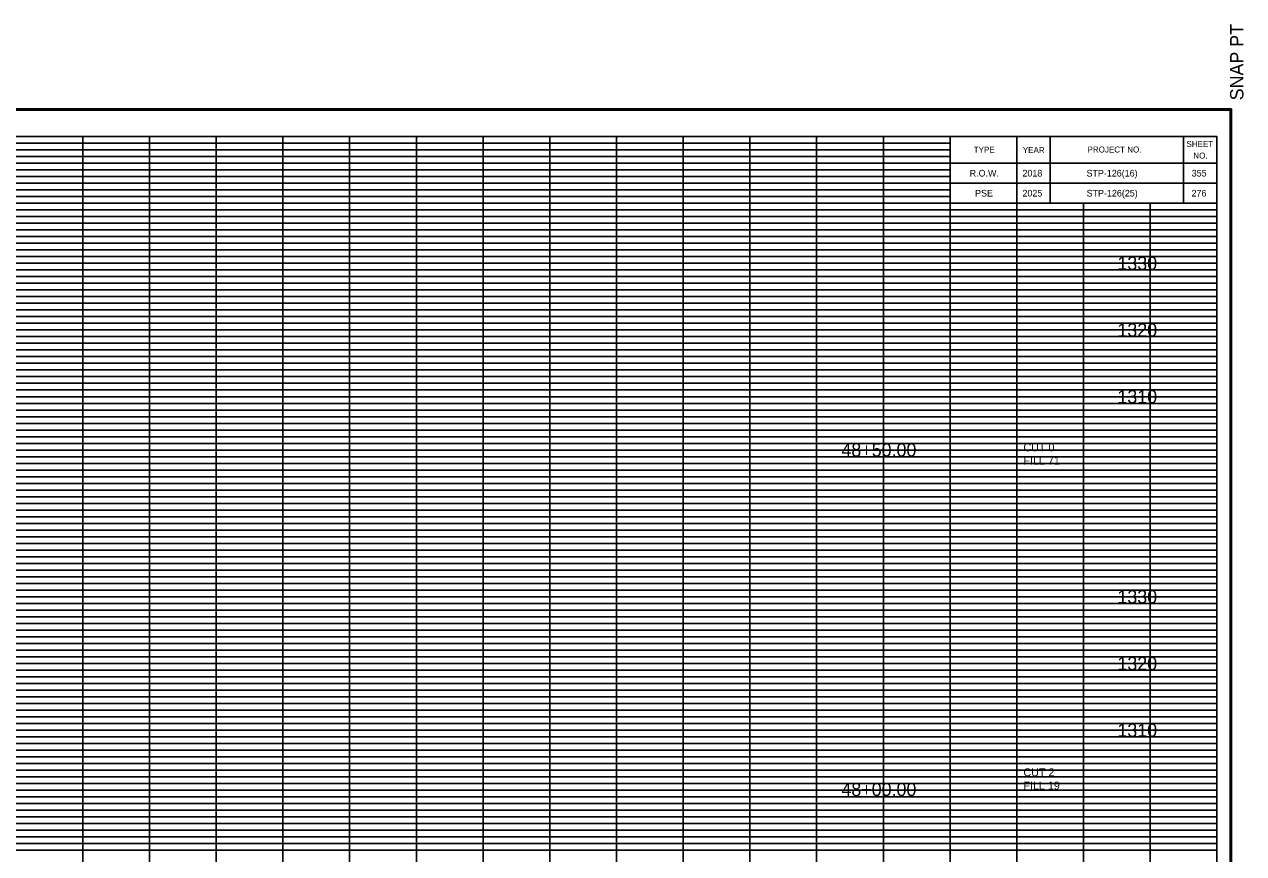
# Model space of a CAD drawing. Extents: x 980 to 1324, y 978 to 1497.
# Drawn here: x 1141.2 to 1324, y 1102.5 to 1226.8 of the extents above; entities that cross this region are included whole.
import ezdxf

# ---------------------------------------------------------------- set-up
doc = ezdxf.new("R2010")
doc.units = 0
for name, color, linetype in [('DESIGN - SCRATCH - User 1', 7, 'Continuous'), ('DESIGN - SHEET - Corner Text', 7, 'Continuous'), ('DESIGN - SHEET - Light Grid', 7, 'Continuous'), ('DESIGN - SHEET - Linework', 7, 'Continuous'), ('DESIGN - SHEET - Plot Shape', 7, 'Continuous'), ('DESIGN - TYPICAL - Finished Grade and Subgrade', 7, 'Continuous'), ('DESIGN - TYPICAL - Text', 7, 'Continuous')]:
    doc.layers.add(name, color=color, linetype=linetype)

# ---------------------------------------------------------------- blocks, each defined once
blk = doc.blocks.new('XSTSHT')
at = {"layer": 'DESIGN - SCRATCH - User 1'}
for p, q in [((28.5, 20.45), (28.5, 20.45)), ((29.24, 20.45), (29.24, 20.45)), ((30.49, 20.45), (30.49, 20.45)), ((31.74, 20.45), (31.74, 20.45)), ((28.5, 20.15), (28.5, 20.15)), ((29.24, 20.15), (29.24, 20.15)), ((30.49, 20.15), (30.49, 20.15)), ((31.74, 20.15), (31.74, 20.15))]:
    blk.add_line(p, q, dxfattribs=at)
at = {"layer": 'DESIGN - SHEET - Light Grid'}
for p, q in [((8, 20.9), (16, 20.9)), ((16, 20.9), (24, 20.9)), ((24, 20.9), (28, 20.9)), ((8, 20.8), (16, 20.8)), ((8, 20.7), (16, 20.7)), ((16, 20.8), (24, 20.8)), ((16, 20.7), (24, 20.7)), ((24, 20.8), (28, 20.8)), ((24, 20.7), (28, 20.7)), ((8, 20.6), (16, 20.6)), ((8, 20.5), (16, 20.5)), ((16, 20.6), (24, 20.6)), ((16, 20.5), (24, 20.5)), ((24, 20.6), (28, 20.6)), ((24, 20.5), (28, 20.5)), ((8, 20.4), (16, 20.4)), ((8, 20.3), (16, 20.3)), ((16, 20.4), (24, 20.4)), ((16, 20.3), (24, 20.3)), ((24, 20.4), (28, 20.4)), ((24, 20.3), (28, 20.3)), ((8, 20.2), (16, 20.2)), ((16, 20.2), (24, 20.2)), ((24, 20.2), (28, 20.2)), ((8, 20.1), (16, 20.1)), ((16, 20.1), (24, 20.1)), ((24, 20.1), (28, 20.1)), ((8, 19.9), (16, 19.9)), ((8, 19.8), (16, 19.8)), ((16, 19.9), (24, 19.9)), ((16, 19.8), (24, 19.8)), ((24, 19.9), (32, 19.9)), ((24, 19.8), (32, 19.8)), ((8, 19.7), (16, 19.7)), ((8, 19.6), (16, 19.6)), ((16, 19.7), (24, 19.7)), ((16, 19.6), (24, 19.6)), ((24, 19.7), (32, 19.7)), ((24, 19.6), (32, 19.6)), ((8, 19.5), (16, 19.5)), ((8, 19.4), (16, 19.4)), ((16, 19.5), (24, 19.5)), ((16, 19.4), (24, 19.4)), ((24, 19.5), (32, 19.5)), ((24, 19.4), (32, 19.4)), ((8, 19.3), (16, 19.3)), ((8, 19.2), (16, 19.2)), ((16, 19.3), (24, 19.3)), ((16, 19.2), (24, 19.2)), ((24, 19.3), (32, 19.3)), ((24, 19.2), (32, 19.2)), ((8, 19.1), (16, 19.1)), ((16, 19.1), (24, 19.1)), ((24, 19.1), (32, 19.1)), ((8, 18.9), (16, 18.9)), ((16, 18.9), (24, 18.9)), ((24, 18.9), (32, 18.9)), ((8, 18.8), (16, 18.8)), ((8, 18.7), (16, 18.7)), ((16, 18.8), (24, 18.8)), ((16, 18.7), (24, 18.7)), ((24, 18.8), (32, 18.8)), ((24, 18.7), (32, 18.7)), ((8, 18.6), (16, 18.6)), ((8, 18.5), (16, 18.5)), ((16, 18.6), (24, 18.6)), ((16, 18.5), (24, 18.5)), ((24, 18.6), (32, 18.6)), ((24, 18.5), (32, 18.5)), ((8, 18.4), (16, 18.4)), ((8, 18.3), (16, 18.3)), ((16, 18.4), (24, 18.4)), ((16, 18.3), (24, 18.3)), ((24, 18.4), (32, 18.4)), ((24, 18.3), (32, 18.3)), ((8, 18.2), (16, 18.2)), ((8, 18.1), (16, 18.1)), ((16, 18.2), (24, 18.2)), ((16, 18.1), (24, 18.1)), ((24, 18.2), (32, 18.2)), ((24, 18.1), (32, 18.1)), ((8, 17.9), (16, 17.9)), ((8, 17.8), (16, 17.8)), ((16, 17.9), (24, 17.9)), ((16, 17.8), (24, 17.8)), ((24, 17.9), (32, 17.9)), ((24, 17.8), (32, 17.8)), ((8, 17.7), (16, 17.7)), ((8, 17.6), (16, 17.6)), ((16, 17.7), (24, 17.7)), ((16, 17.6), (24, 17.6)), ((24, 17.7), (32, 17.7)), ((24, 17.6), (32, 17.6)), ((8, 17.5), (16, 17.5)), ((8, 17.4), (16, 17.4)), ((16, 17.5), (24, 17.5)), ((16, 17.4), (24, 17.4)), ((24, 17.5), (32, 17.5)), ((24, 17.4), (32, 17.4)), ((8, 17.3), (16, 17.3)), ((8, 17.2), (16, 17.2)), ((16, 17.3), (24, 17.3)), ((16, 17.2), (24, 17.2)), ((24, 17.3), (32, 17.3)), ((24, 17.2), (32, 17.2)), ((8, 17.1), (16, 17.1)), ((16, 17.1), (24, 17.1)), ((24, 17.1), (32, 17.1)), ((8, 16.9), (16, 16.9)), ((16, 16.9), (24, 16.9)), ((24, 16.9), (32, 16.9)), ((8, 16.8), (16, 16.8)), ((8, 16.7), (16, 16.7)), ((16, 16.8), (24, 16.8)), ((16, 16.7), (24, 16.7)), ((24, 16.8), (32, 16.8)), ((24, 16.7), (32, 16.7)), ((8, 16.6), (16, 16.6)), ((8, 16.5), (16, 16.5)), ((16, 16.6), (24, 16.6)), ((16, 16.5), (24, 16.5)), ((24, 16.6), (32, 16.6)), ((24, 16.5), (32, 16.5)), ((8, 16.4), (16, 16.4)), ((8, 16.3), (16, 16.3)), ((16, 16.4), (24, 16.4)), ((16, 16.3), (24, 16.3)), ((24, 16.4), (32, 16.4)), ((24, 16.3), (32, 16.3)), ((8, 16.2), (16, 16.2)), ((8, 16.1), (16, 16.1)), ((16, 16.2), (24, 16.2)), ((16, 16.1), (24, 16.1)), ((24, 16.2), (32, 16.2)), ((24, 16.1), (32, 16.1)), ((8, 15.9), (16, 15.9)), ((16, 15.9), (24, 15.9)), ((24, 15.9), (32, 15.9)), ((8, 15.8), (16, 15.8)), ((16, 15.8), (24, 15.8)), ((24, 15.8), (32, 15.8)), ((8, 15.7), (16, 15.7)), ((8, 15.6), (16, 15.6)), ((16, 15.7), (24, 15.7)), ((16, 15.6), (24, 15.6)), ((24, 15.7), (32, 15.7)), ((24, 15.6), (32, 15.6)), ((8, 15.5), (16, 15.5)), ((8, 15.4), (16, 15.4)), ((16, 15.5), (24, 15.5)), ((16, 15.4), (24, 15.4)), ((24, 15.5), (32, 15.5)), ((24, 15.4), (32, 15.4)), ((8, 15.3), (16, 15.3)), ((8, 15.2), (16, 15.2)), ((16, 15.3), (24, 15.3)), ((16, 15.2), (24, 15.2)), ((24, 15.3), (32, 15.3)), ((24, 15.2), (32, 15.2)), ((8, 15.1), (16, 15.1)), ((16, 15.1), (24, 15.1)), ((24, 15.1), (32, 15.1)), ((8, 14.9), (16, 14.9)), ((16, 14.9), (24, 14.9)), ((24, 14.9), (32, 14.9)), ((8, 14.8), (16, 14.8)), ((8, 14.7), (16, 14.7)), ((16, 14.8), (24, 14.8)), ((16, 14.7), (24, 14.7)), ((24, 14.8), (32, 14.8)), ((24, 14.7), (32, 14.7)), ((8, 14.6), (16, 14.6)), ((8, 14.5), (16, 14.5)), ((16, 14.6), (24, 14.6)), ((16, 14.5), (24, 14.5)), ((24, 14.6), (32, 14.6)), ((24, 14.5), (32, 14.5)), ((8, 14.4), (16, 14.4)), ((8, 14.3), (16, 14.3)), ((16, 14.4), (24, 14.4)), ((16, 14.3), (24, 14.3)), ((24, 14.4), (32, 14.4)), ((24, 14.3), (32, 14.3)), ((8, 14.2), (16, 14.2)), ((8, 14.1), (16, 14.1)), ((16, 14.2), (24, 14.2)), ((16, 14.1), (24, 14.1)), ((24, 14.2), (32, 14.2)), ((24, 14.1), (32, 14.1)), ((8, 13.9), (16, 13.9)), ((16, 13.9), (24, 13.9)), ((24, 13.9), (32, 13.9)), ((8, 13.8), (16, 13.8)), ((16, 13.8), (24, 13.8)), ((24, 13.8), (32, 13.8)), ((8, 13.7), (16, 13.7)), ((8, 13.6), (16, 13.6)), ((16, 13.7), (24, 13.7)), ((16, 13.6), (24, 13.6)), ((24, 13.7), (32, 13.7)), ((24, 13.6), (32, 13.6)), ((8, 13.5), (16, 13.5)), ((8, 13.4), (16, 13.4)), ((16, 13.5), (24, 13.5)), ((16, 13.4), (24, 13.4)), ((24, 13.5), (32, 13.5)), ((24, 13.4), (32, 13.4)), ((8, 13.3), (16, 13.3)), ((8, 13.2), (16, 13.2)), ((16, 13.3), (24, 13.3)), ((16, 13.2), (24, 13.2)), ((24, 13.3), (32, 13.3)), ((24, 13.2), (32, 13.2)), ((8, 13.1), (16, 13.1)), ((16, 13.1), (24, 13.1)), ((24, 13.1), (32, 13.1)), ((8, 12.9), (16, 12.9)), ((8, 12.8), (16, 12.8)), ((16, 12.9), (24, 12.9)), ((16, 12.8), (24, 12.8)), ((24, 12.9), (32, 12.9)), ((24, 12.8), (32, 12.8)), ((8, 12.7), (16, 12.7)), ((16, 12.7), (24, 12.7)), ((24, 12.7), (32, 12.7)), ((8, 12.6), (16, 12.6)), ((8, 12.5), (16, 12.5)), ((16, 12.6), (24, 12.6)), ((16, 12.5), (24, 12.5)), ((24, 12.6), (32, 12.6)), ((24, 12.5), (32, 12.5)), ((8, 12.4), (16, 12.4)), ((8, 12.3), (16, 12.3)), ((16, 12.4), (24, 12.4)), ((16, 12.3), (24, 12.3)), ((24, 12.4), (32, 12.4)), ((24, 12.3), (32, 12.3)), ((8, 12.2), (16, 12.2)), ((8, 12.1), (16, 12.1)), ((16, 12.2), (24, 12.2)), ((16, 12.1), (24, 12.1)), ((24, 12.2), (32, 12.2)), ((24, 12.1), (32, 12.1)), ((8, 11.9), (16, 11.9)), ((16, 11.9), (24, 11.9)), ((24, 11.9), (32, 11.9)), ((8, 11.8), (16, 11.8)), ((8, 11.7), (16, 11.7)), ((16, 11.8), (24, 11.8)), ((16, 11.7), (24, 11.7)), ((24, 11.8), (32, 11.8)), ((24, 11.7), (32, 11.7)), ((8, 11.6), (16, 11.6)), ((16, 11.6), (24, 11.6)), ((24, 11.6), (32, 11.6)), ((8, 11.5), (16, 11.5)), ((8, 11.4), (16, 11.4)), ((16, 11.5), (24, 11.5)), ((16, 11.4), (24, 11.4)), ((24, 11.5), (32, 11.5)), ((24, 11.4), (32, 11.4)), ((8, 11.3), (16, 11.3)), ((8, 11.2), (16, 11.2)), ((16, 11.3), (24, 11.3)), ((16, 11.2), (24, 11.2)), ((24, 11.3), (32, 11.3)), ((24, 11.2), (32, 11.2)), ((8, 11.1), (16, 11.1)), ((16, 11.1), (24, 11.1)), ((24, 11.1), (32, 11.1)), ((8, 10.9), (16, 10.9)), ((8, 10.8), (16, 10.8)), ((16, 10.9), (24, 10.9)), ((16, 10.8), (24, 10.8)), ((24, 10.9), (32, 10.9)), ((24, 10.8), (32, 10.8)), ((8, 10.7), (16, 10.7)), ((8, 10.6), (16, 10.6)), ((16, 10.7), (24, 10.7)), ((16, 10.6), (24, 10.6)), ((24, 10.7), (32, 10.7)), ((24, 10.6), (32, 10.6)), ((8, 10.5), (16, 10.5)), ((16, 10.5), (24, 10.5)), ((24, 10.5), (32, 10.5)), ((8, 10.4), (16, 10.4)), ((8, 10.3), (16, 10.3)), ((16, 10.4), (24, 10.4)), ((16, 10.3), (24, 10.3)), ((24, 10.4), (32, 10.4)), ((24, 10.3), (32, 10.3))]:
    blk.add_line(p, q, dxfattribs=at)
at = {"layer": 'DESIGN - SHEET - Linework'}
for p, q in [((-1.823, 21.414), (32.217, 21.414)), ((32.217, 21.414), (32.217, -0.414)), ((15, 0), (15, 21)), ((16, 0), (16, 21)), ((17, 0), (17, 21)), ((18, 0), (18, 21)), ((19, 0), (19, 21)), ((20, 0), (20, 21)), ((21, 0), (21, 21)), ((22, 0), (22, 21)), ((23, 0), (23, 21)), ((24, 0), (24, 21)), ((25, 0), (25, 21)), ((26, 0), (26, 21)), ((27, 0), (27, 21)), ((0, 20), (28, 20)), ((28, 0), (28, 20)), ((29, 0), (29, 20)), ((30, 0), (30, 20)), ((31, 0), (31, 20)), ((0, 19), (32, 19)), ((0, 18), (32, 18)), ((0, 17), (32, 17)), ((0, 16), (32, 16)), ((0, 15), (32, 15)), ((0, 14), (32, 14)), ((0, 13), (32, 13)), ((0, 12), (32, 12)), ((0, 11), (32, 11))]:
    blk.add_line(p, q, dxfattribs=at)
for points in [[(0, 21), (0, 0), (32, 0), (32, 21), (0, 21)], [(28, 21), (28, 20), (32, 20), (32, 21), (31.5, 21), (31.5, 20), (29.5, 20), (29.5, 21), (29, 21), (29, 20), (32, 20), (28, 20), (28, 20.3), (32, 20.3), (32, 20.6), (28, 20.6)]]:
    blk.add_lwpolyline(points, dxfattribs=at)
at = {"layer": 'DESIGN - SHEET - Plot Shape'}
for points in [[(-1.803, 21.394), (32.197, 21.394), (32.197, -0.394), (-1.803, -0.394)], [(-0.85, 21), (32, 21), (32, -0.25), (-0.85, -0.25)]]:
    blk.add_lwpolyline(points, close=True, dxfattribs=at)
at = {"layer": 'DESIGN - SHEET - Corner Text'}
blk.add_text('  SNAP PT', height=0.2, rotation=90, dxfattribs=at).set_placement((32.397, 21.394))
for s, p in [('TYPE', (28.354, 20.756)), ('YEAR', (29.09, 20.752)), ('PROJECT NO.', (30.06, 20.76)), ('SHEET', (31.543, 20.843)), ('NO.', (31.646, 20.669))]:
    blk.add_text(s, height=0.09, dxfattribs=at).set_placement(p)

msp = doc.modelspace()

# ---------------------------------------------------------------- linework, layer by layer
at = {"layer": 'DESIGN - SHEET - Plot Shape'}
msp.add_lwpolyline([(991.5, 997.5), (1320, 997.5), (1320, 1210), (991.5, 1210)], close=True, dxfattribs=at)

# ---------------------------------------------------------------- block references
at = {"layer": 'DESIGN - TYPICAL - Finished Grade and Subgrade', "xscale": 10, "yscale": 10}
msp.add_blockref('XSTSHT', (1000, 1000), dxfattribs=at)

# ---------------------------------------------------------------- texts
at = {"layer": 'DESIGN - SHEET - Corner Text'}
for s, p in [('R.O.W.', (1282.94, 1204)), ('2018', (1290.85, 1204)), ('STP-126(16)', (1300.45, 1204)), ('355', (1316.22, 1204)), ('PSE', (1283.75, 1201)), ('2025', (1290.85, 1201)), ('STP-126(25)', (1300.47, 1201)), ('276', (1316.19, 1201))]:
    msp.add_text(s, height=1, dxfattribs=at).set_placement(p)
at = {"layer": 'DESIGN - TYPICAL - Text'}
for s, height, p in [('     1330     ', 2, (1301.37, 1190)), ('     1320     ', 2, (1301.37, 1180)), ('     1310     ', 2, (1301.37, 1170)), ('     48+50.00     ', 2, (1260, 1162.02)), ('CUT 0', 1.2, (1291, 1162.81)), ('FILL 71', 1.2, (1291, 1160.81)), ('     1330     ', 2, (1301.37, 1140)), ('     1320     ', 2, (1301.37, 1130)), ('     1310     ', 2, (1301.37, 1120)), ('CUT 2', 1.2, (1291, 1114.09)), ('     48+00.00     ', 2, (1260, 1111.13)), ('FILL 19', 1.2, (1291, 1112.09))]:
    msp.add_text(s, height=height, dxfattribs=at).set_placement(p)

doc.saveas('drawing.dxf')
